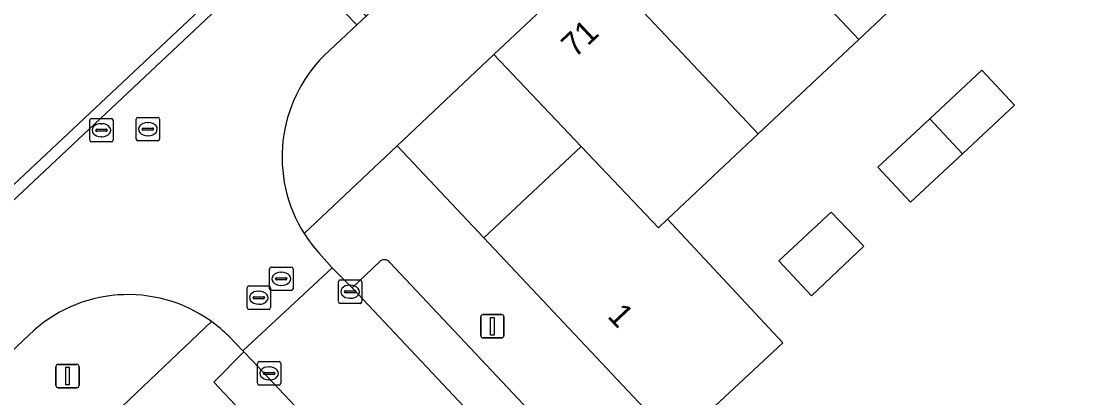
# Model space of a CAD drawing. Extents: x 162542 to 163147, y 380779 to 381521.
# Drawn here: x 162623.92 to 162669.21, y 381283.2 to 381299.29 of the extents above; entities that cross this region are included whole.
import ezdxf

# ---------------------------------------------------------------- set-up
doc = ezdxf.new("R2010")
doc.units = 0
for name, color, linetype in [('IMGEO_Erf', 7, 'Continuous'), ('IMGEO_Kolk', 7, 'Continuous'), ('IMGEO_Lichtmast', 7, 'Continuous'), ('IMGEO_Pand', 7, 'Continuous'), ('IMGEO_Pand_nummerreeks', 7, 'Continuous'), ('IMGEO_Parkeervlak_open', 7, 'Continuous'), ('IMGEO_Rijbaan_lokaal_gesloten', 7, 'Continuous'), ('IMGEO_Rijbaan_lokaal_open', 7, 'Continuous'), ('IMGEO_Rioolput', 7, 'Continuous'), ('IMGEO_Voetpad_open', 7, 'Continuous')]:
    doc.layers.add(name, color=color, linetype=linetype)

msp = doc.modelspace()

# ---------------------------------------------------------------- linework, layer by layer
at = {"layer": 'IMGEO_Erf'}
msp.add_lwpolyline([(162701.836, 381338.243), (162697.562, 381334.216), (162693.632, 381330.514), (162695.682, 381328.338), (162691.153, 381324.068), (162686.962, 381320.117), (162682.772, 381316.167), (162678.582, 381312.217), (162674.392, 381308.266), (162670.202, 381304.316), (162665.608, 381299.985), (162663.544, 381302.142), (162659.684, 381298.508), (162655.396, 381294.471), (162651.525, 381290.827), (162656.442, 381285.541), (162651.893, 381281.31)], dxfattribs=at)
for points in [[(162644.108, 381297.864), (162639.968, 381293.965), (162643.678, 381290.028), (162647.835, 381293.935)], [(162664.116, 381293.626), (162661.892, 381291.557), (162660.504, 381293.049), (162662.726, 381295.119), (162664.948, 381297.19), (162666.339, 381295.695)], [(162659.9, 381289.682), (162657.666, 381287.561), (162656.277, 381289.054), (162658.503, 381291.125)]]:
    msp.add_lwpolyline(points, close=True, dxfattribs=at)
at = {"layer": 'IMGEO_Kolk'}
for p, q in [((162637.464, 381287.306), (162637.464, 381288.158)), ((162637.539, 381288.232), (162638.391, 381288.232)), ((162637.952, 381288.012), (162637.977, 381288.012)), ((162638.465, 381288.158), (162638.465, 381287.306)), ((162637.723, 381287.726), (162637.723, 381287.738)), ((162638.161, 381287.689), (162637.763, 381287.689)), ((162637.766, 381287.775), (162638.164, 381287.775)), ((162637.975, 381287.452), (162637.95, 381287.452)), ((162638.207, 381287.738), (162638.207, 381287.726)), ((162638.391, 381287.232), (162637.539, 381287.232)), ((162634.004, 381283.818), (162634.004, 381284.67)), ((162634.079, 381284.744), (162634.931, 381284.744)), ((162635.005, 381284.67), (162635.005, 381283.818)), ((162634.263, 381284.238), (162634.263, 381284.25)), ((162634.701, 381284.201), (162634.303, 381284.201)), ((162634.306, 381284.287), (162634.704, 381284.287)), ((162634.492, 381284.524), (162634.517, 381284.524)), ((162634.747, 381284.25), (162634.747, 381284.238)), ((162634.931, 381283.744), (162634.079, 381283.744)), ((162634.515, 381283.964), (162634.49, 381283.964))]:
    msp.add_line(p, q, dxfattribs=at)
for points in [[(162637.464, 381287.306), (162637.464, 381288.158)], [(162637.539, 381288.232), (162638.391, 381288.232)], [(162638.465, 381288.158), (162638.465, 381287.306)], [(162638.391, 381287.232), (162637.539, 381287.232)], [(162634.004, 381283.818), (162634.004, 381284.67)], [(162634.079, 381284.744), (162634.931, 381284.744)], [(162635.005, 381284.67), (162635.005, 381283.818)], [(162634.931, 381283.744), (162634.079, 381283.744)]]:
    msp.add_lwpolyline(points, dxfattribs=at)
for centre, radius, start, end in [((162637.541, 381288.156), 0.0765, 91.552, 178.448), ((162637.541, 381288.156), 0.0765, 91.552, 178.448), ((162638.389, 381288.156), 0.0765, 1.552, 88.448), ((162638.389, 381288.156), 0.0765, 1.552, 88.448), ((162637.763, 381287.735), 0.0403, 85.8775, 175.7526), ((162637.76, 381287.725), 0.0366, 178.938, 274.7102), ((162638.164, 381287.732), 0.043, 264.8664, 352.4533), ((162638.168, 381287.737), 0.0386, 1.7309, 96.639), ((162637.541, 381287.308), 0.0765, 181.552, 268.448), ((162637.541, 381287.308), 0.0765, 181.552, 268.448), ((162638.389, 381287.308), 0.0765, 271.552, 358.448), ((162638.389, 381287.308), 0.0765, 271.552, 358.448), ((162634.081, 381284.668), 0.0765, 91.552, 178.448), ((162634.081, 381284.668), 0.0765, 91.552, 178.448), ((162634.929, 381284.668), 0.0765, 1.552, 88.448), ((162634.929, 381284.668), 0.0765, 1.552, 88.448), ((162634.303, 381284.247), 0.0403, 85.8775, 175.7526), ((162634.3, 381284.237), 0.0366, 178.938, 274.7102), ((162634.704, 381284.244), 0.043, 264.8664, 352.4533), ((162634.708, 381284.249), 0.0386, 1.7309, 96.639), ((162634.081, 381283.82), 0.0765, 181.552, 268.448), ((162634.081, 381283.82), 0.0765, 181.552, 268.448), ((162634.929, 381283.82), 0.0765, 271.552, 358.448), ((162634.929, 381283.82), 0.0765, 271.552, 358.448)]:
    msp.add_arc(centre, radius, start, end, dxfattribs=at)
for centre, major_axis, ratio, start_param, end_param in [((162637.951, 381287.732), (-0.387, 0.002), 0.722429, 4.712389, 7.853982), ((162637.976, 381287.732), (-0.39, 0.002), 0.717154, 1.570796, 4.712389), ((162634.491, 381284.244), (-0.387, 0.002), 0.722429, 4.712389, 7.853982), ((162634.516, 381284.244), (-0.39, 0.002), 0.717154, 1.570796, 4.712389)]:
    msp.add_ellipse(centre, major_axis=major_axis, ratio=ratio, start_param=start_param, end_param=end_param, dxfattribs=at)
at = {"layer": 'IMGEO_Lichtmast'}
for p, q in [((162643.54, 381285.855), (162643.54, 381286.655)), ((162643.54, 381286.655), (162643.54, 381285.855)), ((162643.64, 381286.755), (162644.43, 381286.755)), ((162644.43, 381286.755), (162643.64, 381286.755)), ((162644.53, 381286.655), (162644.53, 381285.855)), ((162644.53, 381285.855), (162644.53, 381286.655)), ((162644.43, 381285.755), (162643.64, 381285.755)), ((162643.64, 381285.755), (162644.43, 381285.755)), ((162625.502, 381284.629), (162626.292, 381284.629)), ((162626.292, 381284.629), (162625.502, 381284.629)), ((162625.402, 381283.729), (162625.402, 381284.529)), ((162625.402, 381284.529), (162625.402, 381283.729)), ((162626.392, 381284.529), (162626.392, 381283.729)), ((162626.392, 381283.729), (162626.392, 381284.529)), ((162626.292, 381283.629), (162625.502, 381283.629)), ((162625.502, 381283.629), (162626.292, 381283.629))]:
    msp.add_line(p, q, dxfattribs=at)
for points in [[(162643.96, 381286.63), (162644.11, 381286.63), (162644.11, 381285.88), (162643.96, 381285.88), (162643.96, 381286.63)], [(162625.822, 381284.504), (162625.972, 381284.504), (162625.972, 381283.754), (162625.822, 381283.754), (162625.822, 381284.504)]]:
    msp.add_lwpolyline(points, dxfattribs=at)
for centre, start, end in [((162643.64, 381286.655), 90, 180), ((162643.64, 381286.655), 90, 180), ((162644.43, 381286.655), 0, 90), ((162644.43, 381286.655), 360, 90), ((162643.64, 381285.855), 180, 270), ((162643.64, 381285.855), 180, 270), ((162644.43, 381285.855), 270, 0), ((162644.43, 381285.855), 270, 0), ((162625.502, 381284.529), 90, 180), ((162625.502, 381284.529), 90, 180), ((162626.292, 381284.529), 0, 90), ((162626.292, 381284.529), 360, 90), ((162625.502, 381283.729), 180, 270), ((162625.502, 381283.729), 180, 270), ((162626.292, 381283.729), 270, 0), ((162626.292, 381283.729), 270, 0)]:
    msp.add_arc(centre, 0.1, start, end, dxfattribs=at)
at = {"layer": 'IMGEO_Pand'}
for points in [[(162659.007, 381307.806), (162656.968, 381309.979), (162652.681, 381305.941), (162659.684, 381298.508), (162663.544, 381302.142), (162663.957, 381302.531)], [(162652.681, 381305.941), (162648.395, 381301.902), (162655.396, 381294.471), (162659.684, 381298.508)], [(162648.395, 381301.902), (162644.108, 381297.864), (162647.835, 381293.935), (162651.133, 381290.458), (162651.525, 381290.827), (162655.396, 381294.471)], [(162666.339, 381295.695), (162664.948, 381297.19), (162662.726, 381295.119), (162664.116, 381293.626)], [(162664.116, 381293.626), (162662.726, 381295.119), (162660.504, 381293.049), (162661.892, 381291.557)], [(162651.525, 381290.827), (162651.133, 381290.458), (162647.835, 381293.935), (162643.678, 381290.028), (162651.893, 381281.31), (162656.442, 381285.541)], [(162659.9, 381289.682), (162658.503, 381291.125), (162656.277, 381289.054), (162657.666, 381287.561)]]:
    msp.add_lwpolyline(points, close=True, dxfattribs=at)
at = {"layer": 'IMGEO_Parkeervlak_open'}
for points in [[(162639.217, 381289.002), (162638.045, 381287.891)], [(162638.045, 381287.891), (162646.243, 381279.193), (162647.665, 381280.485), (162639.66, 381288.983)]]:
    msp.add_lwpolyline(points, dxfattribs=at)
msp.add_lwpolyline([(162633.777, 381284.795), (162633.421, 381285.165), (162632.137, 381283.873), (162654.323, 381260.31), (162658.435, 381255.931), (162664.817, 381249.106), (162666.184, 381250.338), (162664.93, 381251.684), (162664.513, 381252.131)], close=True, dxfattribs=at)
msp.add_arc((162639.43, 381288.805), 0.291, 37.8375, 137.2508, dxfattribs=at)
at = {"layer": 'IMGEO_Rijbaan_lokaal_gesloten'}
msp.add_lwpolyline([(162621.016, 381289.891), (162621.357, 381289.553), (162633.69, 381301.157), (162633.362, 381301.5)], close=True, dxfattribs=at)
at = {"layer": 'IMGEO_Rijbaan_lokaal_open'}
for points in [[(162634.718, 381302.775), (162638.252, 381299.13), (162638.648, 381299.503), (162637.438, 381300.78), (162660.822, 381322.724), (162696.641, 381356.52), (162697.846, 381355.236), (162698.242, 381355.618), (162695.195, 381358.844), (162693.99, 381360.119), (162693.589, 381359.733), (162694.788, 381358.46), (162667.161, 381332.527), (162666.539, 381333.186), (162661.519, 381328.209), (162656.967, 381323.696), (162653.774, 381320.694), (162654.124, 381320.293), (162635.442, 381302.837), (162635.132, 381303.165), (162634.718, 381302.775)], [(162636.86, 381297.823), (162638.252, 381299.13), (162634.718, 381302.775), (162633.362, 381301.5), (162633.69, 381301.157), (162621.357, 381289.553), (162621.016, 381289.891), (162619.656, 381288.613)], [(162632.779, 381285.83), (162633.377, 381285.21), (162637.2, 381288.757), (162636.626, 381289.395)], [(162619.656, 381288.613), (162623.196, 381284.872), (162624.252, 381285.886)]]:
    msp.add_lwpolyline(points, dxfattribs=at)
msp.add_lwpolyline([(162647.584, 381277.771), (162646.243, 381279.193), (162638.045, 381287.891), (162637.309, 381288.643), (162637.2, 381288.757), (162633.377, 381285.21), (162633.421, 381285.165), (162633.777, 381284.795), (162664.513, 381252.131), (162664.93, 381251.684), (162668.779, 381255.283), (162665.49, 381258.773), (162664.121, 381260.226)], close=True, dxfattribs=at)
for centre, radius, start, end in [((162641.177, 381293.486), 6.119, 134.8643, 212.2236), ((162641.144, 381293.461), 6.078, 212.1925, 221.9889), ((162628.486, 381281.539), 6.068, 54.1599, 134.2424), ((162628.577, 381281.628), 5.942, 44.9962, 54.3647)]:
    msp.add_arc(centre, radius, start, end, dxfattribs=at)
at = {"layer": 'IMGEO_Rioolput'}
for p, q in [((162626.844, 381294.201), (162626.844, 381295.053)), ((162626.919, 381295.127), (162627.771, 381295.127)), ((162627.845, 381295.053), (162627.845, 381294.201)), ((162628.828, 381294.25), (162628.828, 381295.102)), ((162628.903, 381295.176), (162629.755, 381295.176)), ((162629.829, 381295.102), (162629.829, 381294.25)), ((162627.103, 381294.621), (162627.103, 381294.633)), ((162627.146, 381294.67), (162627.544, 381294.67)), ((162627.332, 381294.907), (162627.357, 381294.907)), ((162627.587, 381294.633), (162627.587, 381294.621)), ((162629.087, 381294.67), (162629.087, 381294.682)), ((162629.525, 381294.633), (162629.127, 381294.633)), ((162629.13, 381294.719), (162629.528, 381294.719)), ((162629.316, 381294.956), (162629.341, 381294.956)), ((162629.571, 381294.682), (162629.571, 381294.67)), ((162627.541, 381294.584), (162627.143, 381294.584)), ((162627.355, 381294.347), (162627.33, 381294.347)), ((162629.755, 381294.176), (162628.903, 381294.176)), ((162629.339, 381294.396), (162629.314, 381294.396)), ((162627.771, 381294.127), (162626.919, 381294.127)), ((162634.524, 381287.857), (162634.524, 381288.709)), ((162634.599, 381288.783), (162635.451, 381288.783)), ((162635.525, 381288.709), (162635.525, 381287.857)), ((162634.783, 381288.277), (162634.783, 381288.289)), ((162634.826, 381288.326), (162635.224, 381288.326)), ((162635.012, 381288.563), (162635.037, 381288.563)), ((162635.267, 381288.289), (162635.267, 381288.277)), ((162633.563, 381287.05), (162633.563, 381287.902)), ((162633.638, 381287.976), (162634.49, 381287.976)), ((162634.564, 381287.902), (162634.564, 381287.05)), ((162635.221, 381288.24), (162634.823, 381288.24)), ((162635.035, 381288.003), (162635.01, 381288.003)), ((162633.822, 381287.47), (162633.822, 381287.482)), ((162634.26, 381287.433), (162633.862, 381287.433)), ((162633.865, 381287.519), (162634.263, 381287.519)), ((162634.051, 381287.756), (162634.076, 381287.756)), ((162634.306, 381287.482), (162634.306, 381287.47)), ((162635.451, 381287.783), (162634.599, 381287.783)), ((162634.49, 381286.976), (162633.638, 381286.976)), ((162634.074, 381287.196), (162634.049, 381287.196))]:
    msp.add_line(p, q, dxfattribs=at)
for points in [[(162626.844, 381294.201), (162626.844, 381295.053)], [(162626.919, 381295.127), (162627.771, 381295.127)], [(162627.845, 381295.053), (162627.845, 381294.201)], [(162628.828, 381294.25), (162628.828, 381295.102)], [(162628.903, 381295.176), (162629.755, 381295.176)], [(162629.829, 381295.102), (162629.829, 381294.25)], [(162629.755, 381294.176), (162628.903, 381294.176)], [(162627.771, 381294.127), (162626.919, 381294.127)], [(162634.524, 381287.857), (162634.524, 381288.709)], [(162634.599, 381288.783), (162635.451, 381288.783)], [(162635.525, 381288.709), (162635.525, 381287.857)], [(162633.563, 381287.05), (162633.563, 381287.902)], [(162633.638, 381287.976), (162634.49, 381287.976)], [(162634.564, 381287.902), (162634.564, 381287.05)], [(162635.451, 381287.783), (162634.599, 381287.783)], [(162634.49, 381286.976), (162633.638, 381286.976)]]:
    msp.add_lwpolyline(points, dxfattribs=at)
for centre, radius, start, end in [((162626.921, 381295.051), 0.0765, 91.552, 178.448), ((162626.921, 381295.051), 0.0765, 91.552, 178.448), ((162627.769, 381295.051), 0.0765, 1.552, 88.448), ((162627.769, 381295.051), 0.0765, 1.552, 88.448), ((162628.905, 381295.1), 0.0765, 91.552, 178.448), ((162628.905, 381295.1), 0.0765, 91.552, 178.448), ((162629.753, 381295.1), 0.0765, 1.552, 88.448), ((162629.753, 381295.1), 0.0765, 1.552, 88.448), ((162627.143, 381294.63), 0.0403, 85.8775, 175.7526), ((162627.14, 381294.62), 0.0366, 178.938, 274.7102), ((162627.544, 381294.627), 0.043, 264.8664, 352.4533), ((162627.548, 381294.632), 0.0386, 1.7309, 96.639), ((162629.127, 381294.679), 0.0403, 85.8775, 175.7526), ((162629.124, 381294.669), 0.0366, 178.938, 274.7102), ((162629.528, 381294.676), 0.043, 264.8664, 352.4533), ((162629.532, 381294.681), 0.0386, 1.7309, 96.639), ((162626.921, 381294.203), 0.0765, 181.552, 268.448), ((162626.921, 381294.203), 0.0765, 181.552, 268.448), ((162627.769, 381294.203), 0.0765, 271.552, 358.448), ((162627.769, 381294.203), 0.0765, 271.552, 358.448), ((162628.905, 381294.252), 0.0765, 181.552, 268.448), ((162628.905, 381294.252), 0.0765, 181.552, 268.448), ((162629.753, 381294.252), 0.0765, 271.552, 358.448), ((162629.753, 381294.252), 0.0765, 271.552, 358.448), ((162634.601, 381288.707), 0.0765, 91.552, 178.448), ((162634.601, 381288.707), 0.0765, 91.552, 178.448), ((162635.449, 381288.707), 0.0765, 1.552, 88.448), ((162635.449, 381288.707), 0.0765, 1.552, 88.448), ((162634.823, 381288.286), 0.0403, 85.8775, 175.7526), ((162634.82, 381288.276), 0.0366, 178.938, 274.7102), ((162635.224, 381288.283), 0.043, 264.8664, 352.4533), ((162635.228, 381288.288), 0.0386, 1.7309, 96.639), ((162633.64, 381287.9), 0.0765, 91.552, 178.448), ((162633.64, 381287.9), 0.0765, 91.552, 178.448), ((162634.488, 381287.9), 0.0765, 1.552, 88.448), ((162634.488, 381287.9), 0.0765, 1.552, 88.448), ((162634.601, 381287.859), 0.0765, 181.552, 268.448), ((162634.601, 381287.859), 0.0765, 181.552, 268.448), ((162635.449, 381287.859), 0.0765, 271.552, 358.448), ((162635.449, 381287.859), 0.0765, 271.552, 358.448), ((162633.862, 381287.479), 0.0403, 85.8775, 175.7526), ((162633.859, 381287.469), 0.0366, 178.938, 274.7102), ((162634.263, 381287.476), 0.043, 264.8664, 352.4533), ((162634.267, 381287.481), 0.0386, 1.7309, 96.639), ((162633.64, 381287.052), 0.0765, 181.552, 268.448), ((162633.64, 381287.052), 0.0765, 181.552, 268.448), ((162634.488, 381287.052), 0.0765, 271.552, 358.448), ((162634.488, 381287.052), 0.0765, 271.552, 358.448)]:
    msp.add_arc(centre, radius, start, end, dxfattribs=at)
for centre, major_axis, ratio, start_param, end_param in [((162627.331, 381294.627), (-0.387, 0.002), 0.722429, 4.712389, 7.853982), ((162627.356, 381294.627), (-0.39, 0.002), 0.717154, 1.570796, 4.712389), ((162629.315, 381294.676), (-0.387, 0.002), 0.722429, 4.712389, 7.853982), ((162629.34, 381294.676), (-0.39, 0.002), 0.717154, 1.570796, 4.712389), ((162635.011, 381288.283), (-0.387, 0.002), 0.722429, 4.712389, 7.853982), ((162635.036, 381288.283), (-0.39, 0.002), 0.717154, 1.570796, 4.712389), ((162634.05, 381287.476), (-0.387, 0.002), 0.722429, 4.712389, 7.853982), ((162634.075, 381287.476), (-0.39, 0.002), 0.717154, 1.570796, 4.712389)]:
    msp.add_ellipse(centre, major_axis=major_axis, ratio=ratio, start_param=start_param, end_param=end_param, dxfattribs=at)
at = {"layer": 'IMGEO_Voetpad_open'}
for points in [[(162636, 381290.223), (162639.968, 381293.965), (162644.108, 381297.864), (162648.395, 381301.902), (162652.681, 381305.941), (162656.968, 381309.979), (162686.301, 381337.602)], [(162638.793, 381299.639), (162638.648, 381299.503), (162638.252, 381299.13), (162636.86, 381297.823)], [(162651.893, 381281.31), (162643.678, 381290.028), (162639.968, 381293.965), (162636, 381290.223)], [(162636.626, 381289.395), (162637.2, 381288.757), (162637.309, 381288.643), (162638.045, 381287.891), (162639.217, 381289.002)], [(162639.66, 381288.983), (162647.665, 381280.485), (162649.002, 381279.066), (162653.1, 381274.715), (162657.257, 381270.294), (162665.547, 381261.505), (162666.912, 381260.058), (162670.664, 381256.08)], [(162611.337, 381266.938), (162615.787, 381271.127), (162624.093, 381278.942), (162628.238, 381282.845), (162632.039, 381286.458)], [(162632.039, 381286.458), (162628.238, 381282.845), (162632.139, 381278.693), (162636.196, 381274.379), (162640.101, 381270.226), (162644.007, 381266.073), (162647.912, 381261.921), (162651.817, 381257.768), (162659.768, 381249.313), (162663.665, 381245.159), (162667.274, 381248.499)], [(162624.252, 381285.886), (162623.196, 381284.872), (162622.812, 381284.503), (162622.72, 381284.415)], [(162632.137, 381283.873), (162633.421, 381285.165), (162633.377, 381285.21), (162632.779, 381285.83)], [(162666.184, 381250.338), (162664.817, 381249.106), (162658.435, 381255.931), (162658.138, 381255.619), (162653.988, 381260.007), (162654.323, 381260.31), (162632.137, 381283.873)]]:
    msp.add_lwpolyline(points, dxfattribs=at)
for centre, radius, start, end in [((162641.177, 381293.486), 6.119, 134.8643, 212.2236), ((162641.144, 381293.461), 6.078, 212.1925, 221.9889), ((162639.43, 381288.805), 0.291, 37.8375, 137.2508), ((162628.486, 381281.539), 6.068, 54.1599, 134.2424), ((162628.577, 381281.628), 5.942, 44.9962, 54.3647)]:
    msp.add_arc(centre, radius, start, end, dxfattribs=at)

# ---------------------------------------------------------------- texts
at = {"layer": 'IMGEO_Pand_nummerreeks'}
for s, rotation, p in [('71', 43.0922, (162647.565, 381297.691)), ('1', 313.0977, (162648.915, 381286.66))]:
    msp.add_text(s, height=1, rotation=rotation, dxfattribs=at).set_placement(p)

doc.saveas('drawing.dxf')
